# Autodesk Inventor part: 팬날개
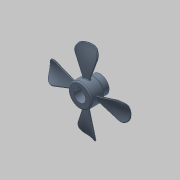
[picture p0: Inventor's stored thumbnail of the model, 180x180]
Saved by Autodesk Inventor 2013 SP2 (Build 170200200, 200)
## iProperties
Company: 한국ATC센터
Created: 2016-06
Part Number: 팬날개
Document SubType Name: Modeling
Designer: mdu
Density: 1.493 g/cm^3
Material: PC/ABS 플라스틱
Mass: 1497.56 g
Surface Area: 466.268 cm^2
Volume: 190.529 cm^3
Author: mdu
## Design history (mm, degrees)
sketch "스케치1"
  geometry: L1 (-15, 0)-(15, 0); L2 (-15, 0)-(-15, 17); L3 (-15, 17)-(5, 17); L4 (5, 17)-(5, 13); L5 (5, 13)-(15, 13); L6 (15, 13)-(15, 0); 2 further points
  constraints: 12 end point, 3 parallel, 2 perpendicular, 1 coincident, 1 horizontal, 1 midpoint
  dimensions: "d0" = 30 distance of L1.start L1.end; "d8" = 34 diameter of L3 L1; "d10" = 26 diameter of L5 L1; "d32" = 20 distance of L2.end L3.end
revolve "회전1" sketch "스케치1" stored, may be unused: angle "d11" = 90 deg
node "작업 평면2"
sketch "스케치7"
  geometry: L1 (-15, 17)-(5, 17) reference; L2 (-15, -17)-(5, -17) reference; L3 (-5, 17)-(-5, -17); A1 r 35 centre (-38.719, -8.43) between (-4, -4) and (-6, 4); 1 further point
  constraints: 2 end point, 2 midpoint, 2 point on circle, 1 centre point
  dimensions: "d36" = 35 radius of A1; "d37" = 13 distance from line of A1.start L2; "d38" = 13 distance from line of A1.end L1; "d45" = 1 distance from line of A1.end L3; "d46" = 1 distance from line of A1.start L3
sketch "3D 스케치1"
  geometry: L1 through (0, 0) direction (1, 0) reference; L2 through (0, 0) direction (1, 0) reference; 13 other entities
  constraints: 2 collinear
  node "투영 원본 위치 스케치7"
sketch "스케치8"
  geometry: L1 (-15, 17)-(5, 17) reference; L2 (-15, -17)-(5, -17) reference; L3 (-5, 17)-(-5, -17); A1 r 30 centre (-28.74, -3.591) between (-3, -19) and (-9, 19); 1 further point
  constraints: 2 end point, 2 midpoint, 2 point on circle, 1 centre point
  dimensions: "d43" = 30 radius of A1; "d47" = 4 distance from line of A1.end L3; "d48" = 2 distance from line of A1.start L3; "d58" = 2 distance from line of A1.end L1; "d59" = 2 distance from line of A1.start L2
sketch "3D 스케치2"
sketch "3D 스케치3"
feature "경계 패치1" sketch "3D 스케치2", "3D 스케치3" dims "d50" = 0
feature "연장1" dims "d55" = 2
feature "두껍게 하기1" dims "d51" = 2, "d52" = 2
sketch "스케치9"
  geometry: C1 r 59 at (0, 0); 1 further point
  constraints: 1 centre point, 1 coincident
  dimensions: "d60" = 118 diameter of C1
extrude "돌출2" sketch "스케치9" distance "d62" = 200; taper "d63" = 0 deg
fillet "모깎기6" dims "d64" = 10
fillet "모깎기7" dims "d66" = 0.8
fillet "모깎기8" dims "d67" = 0.8
sketch "스케치2"
  geometry: L1 (-2.5, 8.124)-(-2.5, 10.8); L2 (-2.5, 10.8)-(2.5, 10.8); L3 (2.5, 10.8)-(2.5, 8.124); A1 r 8.5 centre (0, 0) between (-2.5, 8.124) and (2.5, 8.124); 1 further point
  constraints: 6 end point, 2 parallel, 2 point on circle, 1 centre point, 1 coincident, 1 horizontal, 1 vertical
  dimensions: "d12" = 17 diameter of A1; "d13" = 5 distance of L1.end L2.end; "d14" = 19.3 dimension on A1 L2 (computed from d12)
extrude "돌출1" cut sketch "스케치2" stored distance "d15" = 10; taper "d16" = 0 deg
chamfer "모따기1" distance "d17" = 1; stored, may be unused: second distance "d18" = 2, angle "d19" = 45 deg
node "작업 평면1"
sketch "스케치3"
  geometry: L1 (5, -13)-(5, 13) reference; 3 further points
  constraints: 1 horizontal alignment, 1 midpoint
  dimensions: "d20" = 5 distance from line of L1 point (0, 0)
hole "구멍1" sketch "스케치3" at (0, 0) diameter "d21" = 3.242; stored, may be unused: countersink angle "d25" = 90 deg, drill point angle "d27" = 118 deg; dims "d22" = 6, "d23" = 4, "d24" = 2, "d26" = 8
fillet "모깎기9" dims "d77" = 2
fillet "모깎기10" dims "d78" = 2
fillet "모깎기11" dims "d79" = 2
node "솔리드1"
pattern_circular "원형 패턴1" dims "d69" = 360 deg
pattern_circular "원형 패턴2" dims angle "d72" = 360 deg
pattern_circular "원형 패턴3" dims angle "d75" = 360 deg
node "투영 원본 위치 스케치8"
node "곡면1"
node "곡면2"
node "곡면3"
node "곡면4"
feature "경계 패치2"
feature "경계 패치3"
feature "경계 패치4"
